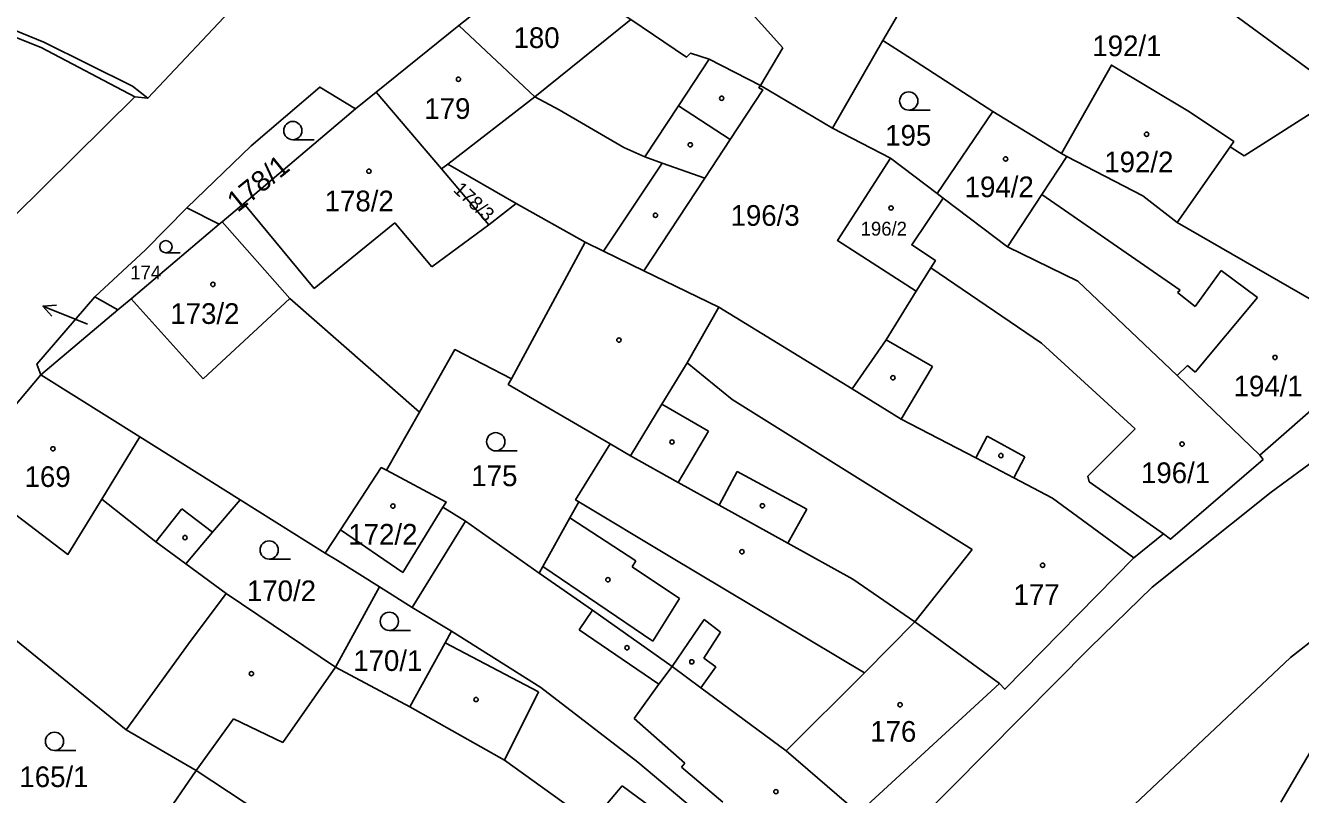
# Model space of a CAD drawing. Extents: x -600849 to -599899, y -1204328 to -1203436.
# Drawn here: x -600469.3 to -600364.4, y -1203635.4 to -1203572.2 of the extents above; entities that cross this region are included whole.
import ezdxf

# ---------------------------------------------------------------- set-up
doc = ezdxf.new("R2010")
doc.units = 0
for name, color, linetype in [('Vrstva 1', 7, 'Continuous'), ('Vrstva 2', 7, 'Continuous'), ('Vrstva 3', 7, 'Continuous'), ('Vrstva 4', 7, 'Continuous'), ('Vrstva 5', 7, 'Continuous'), ('Vrstva 7', 7, 'Continuous')]:
    doc.layers.add(name, color=color, linetype=linetype)

msp = doc.modelspace()

# ---------------------------------------------------------------- linework, layer by layer
at = {"layer": 'Vrstva 1'}
for p, q in [((-600380.45, -1203563.53), (-600361.04, -1203577.78)), ((-600426.94, -1203566.76), (-600433.7, -1203572.2)), ((-600459.28, -1203578.17), (-600451.68, -1203570.07)), ((-600433.7, -1203572.2), (-600440.48, -1203577.67)), ((-600427.43, -1203578.05), (-600433.7, -1203572.2)), ((-600402.94, -1203580.64), (-600398.8, -1203573.43)), ((-600440.48, -1203577.67), (-600442.18, -1203579.05)), ((-600435.11, -1203583.99), (-600440.48, -1203577.67)), ((-600408.88, -1203577.11), (-600402.94, -1203580.64)), ((-600361.04, -1203577.78), (-600369.08, -1203582.92)), ((-600394.32, -1203586.01), (-600389.74, -1203579.26)), ((-600384.09, -1203582.71), (-600389.74, -1203579.26)), ((-600402.94, -1203580.64), (-600398.18, -1203583.09)), ((-600398.18, -1203583.09), (-600394.32, -1203586.01)), ((-600370.23, -1203582.16), (-600374.59, -1203588.39)), ((-600369.08, -1203582.92), (-600370.23, -1203582.16)), ((-600418.47, -1203592.37), (-600413.46, -1203584.75)), ((-600394.32, -1203586.01), (-600393.83, -1203586.38)), ((-600453.42, -1203588.54), (-600456.08, -1203587.18)), ((-600423.3, -1203590), (-600428.97, -1203586.82)), ((-600393.83, -1203586.38), (-600388.55, -1203590.38)), ((-600453.17, -1203588.33), (-600453.42, -1203588.54)), ((-600374.59, -1203588.39), (-600363.54, -1203594.75)), ((-600423.3, -1203590), (-600429.37, -1203601.24)), ((-600412.29, -1203595.36), (-600418.47, -1203592.37)), ((-600461.75, -1203595.57), (-600463.65, -1203594.51)), ((-600468.09, -1203600.92), (-600461.75, -1203595.57)), ((-600401.32, -1203602.08), (-600412.29, -1203595.36)), ((-600358.91, -1203599.75), (-600367.79, -1203607.52)), ((-600439.65, -1203608.76), (-600436.93, -1203603.98)), ((-600367.79, -1203607.52), (-600367.5, -1203607.87)), ((-600451.68, -1203611.2), (-600444.69, -1203615.59)), ((-600378.15, -1203615.98), (-600384.85, -1203611.05)), ((-600433.15, -1203612.96), (-600437.52, -1203620.04)), ((-600433.15, -1203612.96), (-600427.08, -1203617.22)), ((-600375.72, -1203613.98), (-600378.15, -1203615.98)), ((-600452.83, -1203618.9), (-600456.16, -1203616.45)), ((-600440.21, -1203618.35), (-600443.85, -1203624.97)), ((-600440.21, -1203618.35), (-600437.52, -1203620.04)), ((-600443.85, -1203624.97), (-600452.83, -1203618.9)), ((-600437.52, -1203620.04), (-600434.28, -1203622.01)), ((-600461.07, -1203630.12), (-600470.13, -1203622.73)), ((-600437.73, -1203628.23), (-600443.85, -1203624.97)), ((-600400.8, -1203636.96), (-600389.19, -1203626.31)), ((-600361.42, -1203628.14), (-600366.05, -1203636.05)), ((-600455.29, -1203633.46), (-600461.07, -1203630.12)), ((-600443.46, -1203641.26), (-600455.29, -1203633.46))]:
    msp.add_line(p, q, dxfattribs=at)
for points in [[(-600468.32, -1203708.8), (-600459.02, -1203700.91), (-600447.7, -1203689.53), (-600398.8, -1203640.57), (-600381.76, -1203623.36), (-600376.64, -1203618.38), (-600366.85, -1203610.56), (-600358.79, -1203604.64), (-600335.27, -1203586.75), (-600326.92, -1203580.15), (-600315.47, -1203571.41), (-600313.87, -1203569.96), (-600309.19, -1203565.44), (-600307.64, -1203563.87), (-600297.75, -1203553.71), (-600294.09, -1203550.64), (-600277.89, -1203537.3), (-600263.22, -1203524.94), (-600248.8, -1203512.9), (-600231.21, -1203497.85)], [(-600516.74, -1203754.05), (-600500.93, -1203742.85), (-600482.23, -1203729.97), (-600472.33, -1203722.55), (-600463.46, -1203715.87), (-600456.83, -1203710.5), (-600450.71, -1203706.1), (-600424.21, -1203680.79), (-600406.92, -1203664.19), (-600381.77, -1203639.93), (-600378.09, -1203636.25), (-600365.25, -1203624.15), (-600362.86, -1203622.3), (-600356.33, -1203617.3), (-600346.34, -1203609.78), (-600334.21, -1203600.46), (-600309.35, -1203581.63), (-600259.57, -1203537.67), (-600253.46, -1203531.77)], [(-600459.28, -1203578.17), (-600460.53, -1203577.18), (-600467.84, -1203573.55), (-600475.84, -1203570.31), (-600482.56, -1203567.9), (-600486.26, -1203566.43)], [(-600408.88, -1203577.11), (-600413.09, -1203574.96), (-600414.64, -1203574.47), (-600414.95, -1203574.78), (-600419.55, -1203571.7), (-600426.94, -1203566.76)], [(-600398.8, -1203573.43), (-600397.8, -1203571.7), (-600397.54, -1203571.26)], [(-600389.74, -1203579.26), (-600396.05, -1203575.17), (-600398.8, -1203573.43)], [(-600370.23, -1203582.16), (-600369.93, -1203581.73), (-600373.58, -1203579.29), (-600380, -1203575.45), (-600384.09, -1203582.71)], [(-600442.18, -1203579.05), (-600445.14, -1203577.26), (-600450.78, -1203582.08), (-600456.08, -1203587.18)], [(-600413.46, -1203584.75), (-600411.36, -1203581.56), (-600408.68, -1203577.49), (-600409, -1203577.31), (-600408.88, -1203577.11)], [(-600470.3, -1203587.91), (-600460.35, -1203578.05), (-600459.28, -1203578.17)], [(-600418.39, -1203583), (-600420.11, -1203582.23), (-600425.43, -1203579.12), (-600427.43, -1203578.05)], [(-600453.17, -1203588.33), (-600451.39, -1203586.83), (-600442.18, -1203579.05)], [(-600413.46, -1203584.75), (-600416.95, -1203583.51), (-600418.39, -1203583)], [(-600398.18, -1203583.09), (-600402.52, -1203589.88), (-600396.05, -1203594.05)], [(-600383.66, -1203582.95), (-600385.72, -1203586.08), (-600388.55, -1203590.38)], [(-600383.66, -1203582.95), (-600383.95, -1203582.8), (-600384.09, -1203582.71)], [(-600374.59, -1203588.39), (-600377.42, -1203586.19), (-600383.66, -1203582.95)], [(-600435.11, -1203583.99), (-600434.6, -1203583.6), (-600428.97, -1203586.82)], [(-600428.97, -1203586.82), (-600431.23, -1203588.57), (-600435.11, -1203583.99)], [(-600456.08, -1203587.18), (-600459.46, -1203590.63), (-600463.65, -1203594.51)], [(-600393.83, -1203586.38), (-600396.42, -1203590.24), (-600394.47, -1203591.52), (-600394.86, -1203592.13), (-600396.05, -1203594.05)], [(-600436.93, -1203603.98), (-600447.6, -1203594.65), (-600453.17, -1203588.33)], [(-600453.42, -1203588.54), (-600460.65, -1203594.66), (-600461.75, -1203595.57)], [(-600418.47, -1203592.37), (-600421.8, -1203590.74), (-600423.3, -1203590)], [(-600388.55, -1203590.38), (-600382.75, -1203593.21), (-600374.59, -1203600.96), (-600367.79, -1203607.52)], [(-600463.65, -1203594.51), (-600468.41, -1203600.03), (-600468.09, -1203600.92)], [(-600396.05, -1203594.05), (-600398.52, -1203598.04), (-600401.32, -1203602.08)], [(-600429.37, -1203601.24), (-600434.01, -1203598.84), (-600436.93, -1203603.98)], [(-600468.09, -1203600.92), (-600471.57, -1203605.02), (-600473.16, -1203603.87)], [(-600451.68, -1203611.2), (-600459.93, -1203606.03), (-600468.09, -1203600.92)], [(-600421.24, -1203606.59), (-600429.63, -1203601.7), (-600429.37, -1203601.24)], [(-600384.85, -1203611.05), (-600388.01, -1203609.4), (-600391.16, -1203607.75), (-600397.28, -1203604.55), (-600401.32, -1203602.08)], [(-600427.08, -1203617.22), (-600426.79, -1203616.69), (-600424.55, -1203612.69), (-600423.81, -1203611.37), (-600424.09, -1203611.2), (-600421.24, -1203606.59)], [(-600389.19, -1203626.31), (-600396.16, -1203621.24), (-600401.28, -1203617.71), (-600406.61, -1203614.77), (-600412.28, -1203611.63), (-600415.64, -1203609.77), (-600419.57, -1203607.57), (-600421.24, -1203606.59)], [(-600367.5, -1203607.87), (-600375.12, -1203614.44), (-600375.72, -1203613.98)], [(-600456.16, -1203616.45), (-600458.62, -1203614.64), (-600463.06, -1203611.14), (-600465.85, -1203615.69), (-600474.44, -1203609.18), (-600476.47, -1203611.59), (-600478.86, -1203609.57)], [(-600444.69, -1203615.59), (-600443.43, -1203613.67), (-600440.08, -1203608.54), (-600439.65, -1203608.76)], [(-600439.65, -1203608.76), (-600434.73, -1203611.38), (-600435, -1203611.81), (-600433.15, -1203612.96)], [(-600456.16, -1203616.45), (-600453.95, -1203613.86), (-600451.68, -1203611.2)], [(-600444.69, -1203615.59), (-600443.66, -1203616.18), (-600440.21, -1203618.35)], [(-600389.19, -1203626.31), (-600388.76, -1203626.77), (-600378.15, -1203615.98)], [(-600427.08, -1203617.22), (-600422.7, -1203620.26), (-600416.14, -1203624.9)], [(-600461.07, -1203630.12), (-600455.93, -1203623.03), (-600452.83, -1203618.9)], [(-600434.28, -1203622.01), (-600434.81, -1203622.96), (-600437.73, -1203628.23)], [(-600407.05, -1203643.1), (-600413.28, -1203637.54), (-600418.97, -1203632.78), (-600426.95, -1203626.62), (-600434.28, -1203622.01)], [(-600416.14, -1203624.9), (-600413.77, -1203626.66), (-600406.75, -1203631.83), (-600400.8, -1203636.96)], [(-600437.73, -1203628.23), (-600429.94, -1203632.61), (-600422.81, -1203637.72), (-600412.1, -1203648.35)], [(-600461.92, -1203642.39), (-600458.12, -1203637.56), (-600455.29, -1203633.46)]]:
    msp.add_lwpolyline(points, dxfattribs=at)
at = {"layer": 'Vrstva 3'}
for p, q in [((-600396.67, -1203579.15), (-600394.92, -1203579.15)), ((-600447.35, -1203581.58), (-600445.6, -1203581.58)), ((-600457.79, -1203590.88), (-600456.61, -1203590.88)), ((-600430.65, -1203607.17), (-600428.9, -1203607.17)), ((-600449.3, -1203616.07), (-600447.55, -1203616.07)), ((-600439.41, -1203621.94), (-600437.66, -1203621.94)), ((-600466.96, -1203631.81), (-600465.21, -1203631.81))]:
    msp.add_line(p, q, dxfattribs=at)
for centre, radius in [((-600396.67, -1203578.4), 0.75), ((-600447.35, -1203580.83), 0.75), ((-600457.79, -1203590.38), 0.502), ((-600430.65, -1203606.42), 0.75), ((-600449.3, -1203615.32), 0.75), ((-600439.41, -1203621.19), 0.75), ((-600466.96, -1203631.06), 0.75)]:
    msp.add_circle(centre, radius, dxfattribs=at)
at = {"layer": 'Vrstva 4'}
for p, q in [((-600407.04, -1203574.02), (-600410.53, -1203570.12)), ((-600476.04, -1203570.79), (-600468.07, -1203574.01)), ((-600427.43, -1203578.05), (-600419.55, -1203571.7)), ((-600468.07, -1203574.01), (-600460.35, -1203578.05)), ((-600408.88, -1203577.11), (-600407.04, -1203574.02)), ((-600413.09, -1203574.96), (-600415.61, -1203578.79)), ((-600434.6, -1203583.6), (-600427.43, -1203578.05)), ((-600415.61, -1203578.79), (-600418.39, -1203583)), ((-600415.61, -1203578.79), (-600411.36, -1203581.56)), ((-600416.95, -1203583.51), (-600421.8, -1203590.74)), ((-600374.34, -1203593.96), (-600385.72, -1203586.08)), ((-600451.39, -1203586.83), (-600445.6, -1203593.82)), ((-600445.6, -1203593.82), (-600438.96, -1203588.41)), ((-600438.96, -1203588.41), (-600435.92, -1203592.03)), ((-600435.92, -1203592.03), (-600431.23, -1203588.57)), ((-600394.86, -1203592.13), (-600385.75, -1203598.3)), ((-600370.95, -1203592.34), (-600373.11, -1203595.29)), ((-600367.97, -1203594.55), (-600370.95, -1203592.34)), ((-600460.65, -1203594.66), (-600454.73, -1203601.24)), ((-600454.73, -1203601.24), (-600447.6, -1203594.65)), ((-600374.55, -1203594.15), (-600374.34, -1203593.96)), ((-600373.11, -1203595.29), (-600374.55, -1203594.15)), ((-600373.11, -1203600.71), (-600367.97, -1203594.55)), ((-600414.91, -1203599.93), (-600412.29, -1203595.36)), ((-600398.52, -1203598.04), (-600394.71, -1203600.24)), ((-600385.75, -1203598.3), (-600378.04, -1203605.35)), ((-600417, -1203603.32), (-600414.91, -1203599.93)), ((-600411.2, -1203602.94), (-600414.91, -1203599.93)), ((-600394.71, -1203600.24), (-600397.28, -1203604.55)), ((-600374.59, -1203600.96), (-600373.74, -1203600.14)), ((-600373.74, -1203600.14), (-600373.11, -1203600.71)), ((-600391.46, -1203615.28), (-600411.2, -1203602.94)), ((-600419.57, -1203607.57), (-600417, -1203603.32)), ((-600413.14, -1203605.56), (-600417, -1203603.32)), ((-600463.06, -1203611.14), (-600459.93, -1203606.03)), ((-600415.64, -1203609.77), (-600413.14, -1203605.56)), ((-600390.22, -1203605.96), (-600391.16, -1203607.75)), ((-600390.22, -1203605.96), (-600387.12, -1203607.65)), ((-600378.04, -1203605.35), (-600381.93, -1203609.25)), ((-600387.12, -1203607.65), (-600388.01, -1203609.4)), ((-600412.28, -1203611.63), (-600410.8, -1203608.86)), ((-600410.8, -1203608.86), (-600405.05, -1203611.96)), ((-600381.93, -1203609.25), (-600381.83, -1203609.71)), ((-600381.83, -1203609.71), (-600375.72, -1203613.98)), ((-600423.81, -1203611.37), (-600416.33, -1203615.85)), ((-600458.62, -1203614.64), (-600456.47, -1203611.93)), ((-600456.47, -1203611.93), (-600453.95, -1203613.86)), ((-600435, -1203611.81), (-600438.29, -1203617.18)), ((-600405.05, -1203611.96), (-600406.61, -1203614.77)), ((-600419.13, -1203616.21), (-600424.55, -1203612.69)), ((-600438.29, -1203617.18), (-600443.43, -1203613.67)), ((-600396.16, -1203621.24), (-600391.46, -1203615.28)), ((-600417.73, -1203622.83), (-600426.79, -1203616.69)), ((-600419.13, -1203616.21), (-600419.44, -1203616.72)), ((-600419.44, -1203616.72), (-600415.54, -1203619.3)), ((-600416.33, -1203615.85), (-600400.32, -1203625.42)), ((-600415.54, -1203619.3), (-600417.73, -1203622.83)), ((-600422.7, -1203620.26), (-600423.79, -1203621.9)), ((-600423.79, -1203621.9), (-600417.22, -1203626.37)), ((-600416.14, -1203624.9), (-600413.5, -1203621.04)), ((-600413.5, -1203621.04), (-600412.15, -1203622.08)), ((-600400.32, -1203625.42), (-600396.16, -1203621.24)), ((-600434.81, -1203622.96), (-600427.13, -1203627)), ((-600412.15, -1203622.08), (-600413.54, -1203624.22)), ((-600443.85, -1203624.97), (-600448.16, -1203631.15)), ((-600416.14, -1203624.9), (-600417.22, -1203626.37)), ((-600412.55, -1203624.92), (-600413.77, -1203626.66)), ((-600413.54, -1203624.22), (-600412.55, -1203624.92)), ((-600406.75, -1203631.83), (-600400.32, -1203625.42)), ((-600427.13, -1203627), (-600429.94, -1203632.61)), ((-600417.22, -1203626.37), (-600419.27, -1203629.17)), ((-600452.24, -1203629.22), (-600455.29, -1203633.46)), ((-600448.16, -1203631.15), (-600452.24, -1203629.22)), ((-600419.27, -1203629.17), (-600415.09, -1203632.85)), ((-600415.09, -1203632.85), (-600415.38, -1203633.17)), ((-600415.38, -1203633.17), (-600411.97, -1203636.06)), ((-600420.26, -1203634.71), (-600422.81, -1203637.72)), ((-600417.85, -1203636.49), (-600420.26, -1203634.71))]:
    msp.add_line(p, q, dxfattribs=at)
at = {"layer": 'Vrstva 5'}
for centre in [(-600433.72, -1203576.61), (-600412.06, -1203578.17), (-600377.1, -1203581.13), (-600414.65, -1203582), (-600388.7, -1203583.16), (-600441.09, -1203584.17), (-600398.12, -1203587.2), (-600417.51, -1203587.79), (-600453.93, -1203593.48), (-600420.52, -1203598.06), (-600366.53, -1203599.49), (-600397.97, -1203601.16), (-600467.09, -1203607), (-600416.15, -1203606.44), (-600374.18, -1203606.61), (-600389.09, -1203607.56), (-600439.12, -1203611.71), (-600408.71, -1203611.69), (-600456.22, -1203614.3), (-600410.4, -1203615.47), (-600385.66, -1203616.58), (-600421.42, -1203617.77), (-600419.85, -1203623.36), (-600414.52, -1203624.52), (-600450.76, -1203625.49), (-600432.27, -1203627.62), (-600397.38, -1203628.05), (-600407.6, -1203635.2)]:
    msp.add_circle(centre, 0.175, dxfattribs=at)
at = {"layer": 'Vrstva 7'}
for p, q in [((-600467.91, -1203595.27), (-600466.8, -1203595.18)), ((-600465.13, -1203596.39), (-600467.91, -1203595.27)), ((-600467.91, -1203595.27), (-600467.17, -1203596.1)), ((-600464.25, -1203596.74), (-600465.13, -1203596.39))]:
    msp.add_line(p, q, dxfattribs=at)

# ---------------------------------------------------------------- texts
at = {"layer": 'Vrstva 2'}
for s, height, p in [('180', 1.7, (-600429.19, -1203574.04)), ('192/1', 1.7, (-600381.56, -1203574.71)), ('179', 1.7, (-600436.53, -1203579.87)), ('195', 1.7, (-600398.61, -1203582.07)), ('192/2', 1.7, (-600380.58, -1203584.26)), ('194/2', 1.7, (-600392.07, -1203586.31)), ('178/2', 1.7, (-600444.73, -1203587.47)), ('196/3', 1.7, (-600411.33, -1203588.66)), ('196/2', 1.14, (-600400.63, -1203589.47)), ('174', 1.14, (-600460.73, -1203593.07)), ('173/2', 1.7, (-600457.43, -1203596.73)), ('194/1', 1.7, (-600369.94, -1203602.69)), ('196/1', 1.7, (-600377.56, -1203609.82)), ('169', 1.7, (-600469.42, -1203610.14)), ('175', 1.7, (-600432.66, -1203610.07)), ('172/2', 1.7, (-600442.78, -1203614.88)), ('170/2', 1.7, (-600451.13, -1203619.53)), ('177', 1.7, (-600388.05, -1203619.84)), ('170/1', 1.7, (-600442.38, -1203625.27)), ('176', 1.7, (-600399.84, -1203631.09)), ('165/1', 1.7, (-600469.85, -1203634.82))]:
    msp.add_text(s, height=height, dxfattribs=at).set_placement(p)
for s, height, rotation, p in [('178/1', 1.7, 39, (-600451.89, -1203587.61)), ('178/3', 1.14, 317, (-600434.22, -1203585.78))]:
    msp.add_text(s, height=height, rotation=rotation, dxfattribs=at).set_placement(p)

doc.saveas('drawing.dxf')
